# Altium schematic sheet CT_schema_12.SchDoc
size 146 x 119 mm
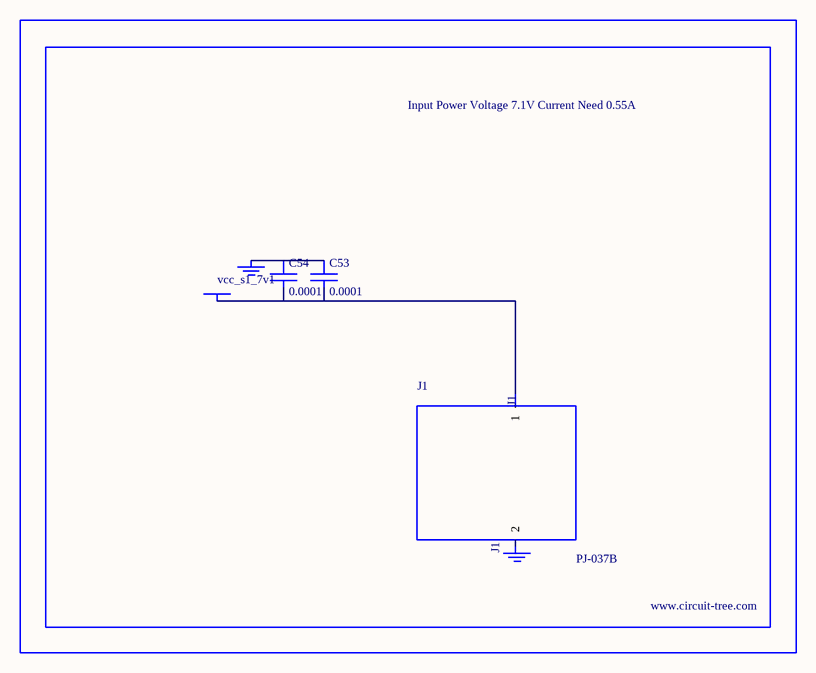
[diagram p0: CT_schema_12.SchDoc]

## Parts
BORDER11  (no value)
C53  0.0001  [EXV-9H]
C54  0.0001  [EXV-9H]
GND_INSTANCE_11_0  (no value)
GND_INSTANCE_11_1  (no value)
J1  PJ-037B  [PJ-037B_PACKAGE]
POWER_INSTANCE_11_0  vcc_s1_7v1

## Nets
NetC53_1: C53.1 C54.1 GND_INSTANCE_11_0.0(GND)
NetC53_2: C53.2 C54.2 J1.1 POWER_INSTANCE_11_0.0(PWR)

Not connected (* = marked no-connect by the designer): GND_INSTANCE_11_1 0(GND); J1 2

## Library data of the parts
BORDER11 = BORDER_PAGE11
C53 C54 = EDK107M035A9HAA
GND_INSTANCE_11_0 GND_INSTANCE_11_1 = GND
POWER_INSTANCE_11_0 = PWR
